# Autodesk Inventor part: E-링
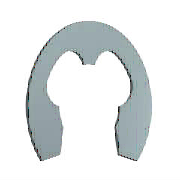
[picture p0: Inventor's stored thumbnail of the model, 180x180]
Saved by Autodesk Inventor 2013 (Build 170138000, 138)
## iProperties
IsCustomPart: 1
Created: 2012-02
Part Number: E-링
Material: 강철, 연강
Description: 일반용 테이퍼 및 줄어든 횡단면 리테이닝 링 - E-링 외부 시리즈 3CM1 리테이닝 링
Document SubType Name: Modeling
Standard: ANSI B27.7
Designer: mduedu
Standard Revision: 1999
Standards Organization: ANSI
Language: ko-KR
Size Designation: 6
Categories: <MemberInstance><Categories><Category DisplayName="샤프트 부품" InternalName="7f7aeb1f-a693-4053-b835-cee3144e0d98" Mnemonic="SHFT"><Category DisplayName="써클립" Inter
Density: 7.86 g/cm^3
Mass: 0.226141 g
Surface Area: 1.26477 cm^2
Volume: 0.0287712 cm^3
Author: mduedu
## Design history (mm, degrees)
sketch "스케치1"
  geometry: L1 (-0.485, 0.024)-(0, 0.024) reference; L2 (-3.206, 0)-(3.486, 0) reference; L3 (-2.223, -3.946)-(2.223, -3.946); L4 (0, 1.949)-(0, -3.479) reference; L5 (-2.91, -2.006)-(-2.435, -2.006); L6 (-0.485, -0.066)-(-0.485, 0.405); L7 (0, 2.574)-(2.53, 2.574); L8 (-2.223, -3.946)-(-3.022, -6.291); L9 (0, -0.551)-(-1.278, -0.551); L10 (2.223, -3.946)-(3.022, -6.291); L11 (2.91, -2.006)-(2.435, -2.006); L12 (0.485, -0.066)-(0.485, 0.405); C1 r 3 at (0, -2.976); A1 r 2.425 centre (0, -2.976) between (-2.297, -2.199) and (-2.223, -3.946); A2 r 0.485 centre (0, -0.066) between (-0.485, -0.066) and (0.485, -0.066); A3 r 5.55 centre (0, -2.976) between (4.27, -6.521) and (-4.27, -6.521); A4 r 3.88 centre (0, -2.976) between (-0.97, 0.78) and (-3.424, -1.15); A5 r 0.388 centre (-0.873, 0.405) between (-0.485, 0.405) and (-0.97, 0.78); A6 r 0.582 centre (-2.91, -1.424) between (-3.424, -1.15) and (-2.91, -2.006); A7 r 0.145 centre (-2.435, -2.152) between (-2.297, -2.199) and (-2.435, -2.006); A8 r 0.727 centre (-3.711, -6.057) between (-4.27, -6.521) and (-3.022, -6.291); A9 r 0.727 centre (3.711, -6.057) between (3.022, -6.291) and (4.27, -6.521); A10 r 2.425 centre (0, -2.976) between (2.223, -3.946) and (2.297, -2.199); A11 r 0.145 centre (2.435, -2.152) between (2.435, -2.006) and (2.297, -2.199); A12 r 0.582 centre (2.91, -1.424) between (2.91, -2.006) and (3.424, -1.15); A13 r 3.88 centre (0, -2.976) between (3.424, -1.15) and (0.97, 0.78); A14 r 0.388 centre (0.873, 0.405) between (0.97, 0.78) and (0.485, 0.405); 1 further point
  constraints: 30 point on circle, 20 end point, 15 centre point, 13 symmetric about line, 12 tangent, 8 point on line, 4 parallel, 2 coincident, 2 horizontal, 1 concentric, 1 perpendicular, 1 vertical alignment, 9 other
  dimensions: "d0" = 6 diameter of C1 (= WD); "d3" = 0.97 distance from line of A1.centre L3 (= 0.2 x ND); "d4" = 0.485 radius of A2 (= 0.1 x ND); "d5" = 11.1 diameter of A3 (= SD2); "d8" = 3.88 radius of A4 (= 0.8 x ND); "d9" = 0.97 distance from line of A1.centre L5 (= 0.2 x ND); "d10" = 0.388 radius of A5 (= 0.08 x ND); "d11" = 0.582 radius of A6 (= 0.12 x ND); "d12" = 0.1455 radius of A7 (= 0.03 x ND); "d13" = 0.7275 radius of A8 (= 0.15 x ND); "d14" = 2.425 distance from line of A1.centre L9 (= 0.5 x ND); "d15" = 2.425 radius of A1 (= 0.5 x ND)
extrude "본체" new body sketch "스케치1" distance "d16" = 0.6 (= SD); taper "d17" = 0 deg
workaxis "Work Axis1"
workaxis "Work Axis2"
workplane "Work Plane1"
body "Solid1"
other parameters: "ND" = 4.85 [user parameter; used in 14 equation terms], "SD" = 0.6 [user parameter; used in 1 equation term], "WD" = 6 (= WDMIN) [user parameter; used in 1 equation term], "d1" = 7.76 (= 1.6 x ND), "d2" = 4.85 (= ND), "SD2" = 11.1 [user parameter; used in 1 equation term], "d6" = 4.85 (= ND), "d7" = 0.7275 (= 0.15 x ND), "d18" = 0, "d19" = 0, "d27" = 0, "d28" = 0, "WDMIN" = 6 [user parameter; used in 1 equation term], "SNB" = 0.7 [user parameter], "WDMAX" = 7 [user parameter], "BUBRMI" = 1.2 [user parameter]
